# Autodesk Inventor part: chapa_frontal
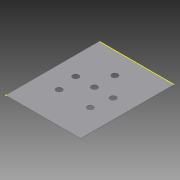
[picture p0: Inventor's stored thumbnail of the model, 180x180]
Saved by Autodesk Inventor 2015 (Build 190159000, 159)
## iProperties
Created: 2016-04
Part Number: chapa_frontal
Material: Genérico
Document SubType Name: Modeling
Designer: Diego
Density: 1 g/cm^3
Appearance: Valor por defecto
Author: Diego
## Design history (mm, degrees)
sketch "Boceto1"
  geometry: L1 (0, 0)-(240, 0); L2 (240, 0)-(240, 300); L3 (240, 300)-(0, 300); L4 (0, 300)-(0, 0)
  constraints: 8 end point, 2 parallel, 1 horizontal, 1 perpendicular
  dimensions: "d0" = 240 distance of L3.end L2.end; "d1" = 300 distance of L2.end L1.end
extrude "Extrusión1" new body sketch "Boceto1" distance "d2" = 1; taper "d3" = 0 deg
sketch "Boceto2"
  geometry: L1 (240, 300)-(0, 300) reference; 1 further point
sketch "Boceto3"
  geometry: L1 (0, 0)-(0, 100); L2 (0, 300)-(0, 0) reference; L3 (240, 0)-(240, 300) reference; L4 (0, 100)-(0, 165); L5 (0, 165)-(0, 230); 7 further points
  constraints: 6 end point, 3 point on line, 1 coincident
  dimensions: "d4" = 100 distance of L1.start L1.end; "d5" = 65 distance of L1.end L4.end; "d6" = 65 distance of L4.end L5.end
hole "Agujero1" sketch "Boceto3" at (120, 230), (60, 164.252), (70, 100.852), (120, 164.252), (180, 164.252), (170, 100.852) diameter "d7" = 20; stored, may be unused: countersink angle "d11" = 90 deg, drill point angle "d13" = 118 deg; dims "d8" = 6, "d9" = 4, "d10" = 2, "d12" = 8
node "Sólido1"
